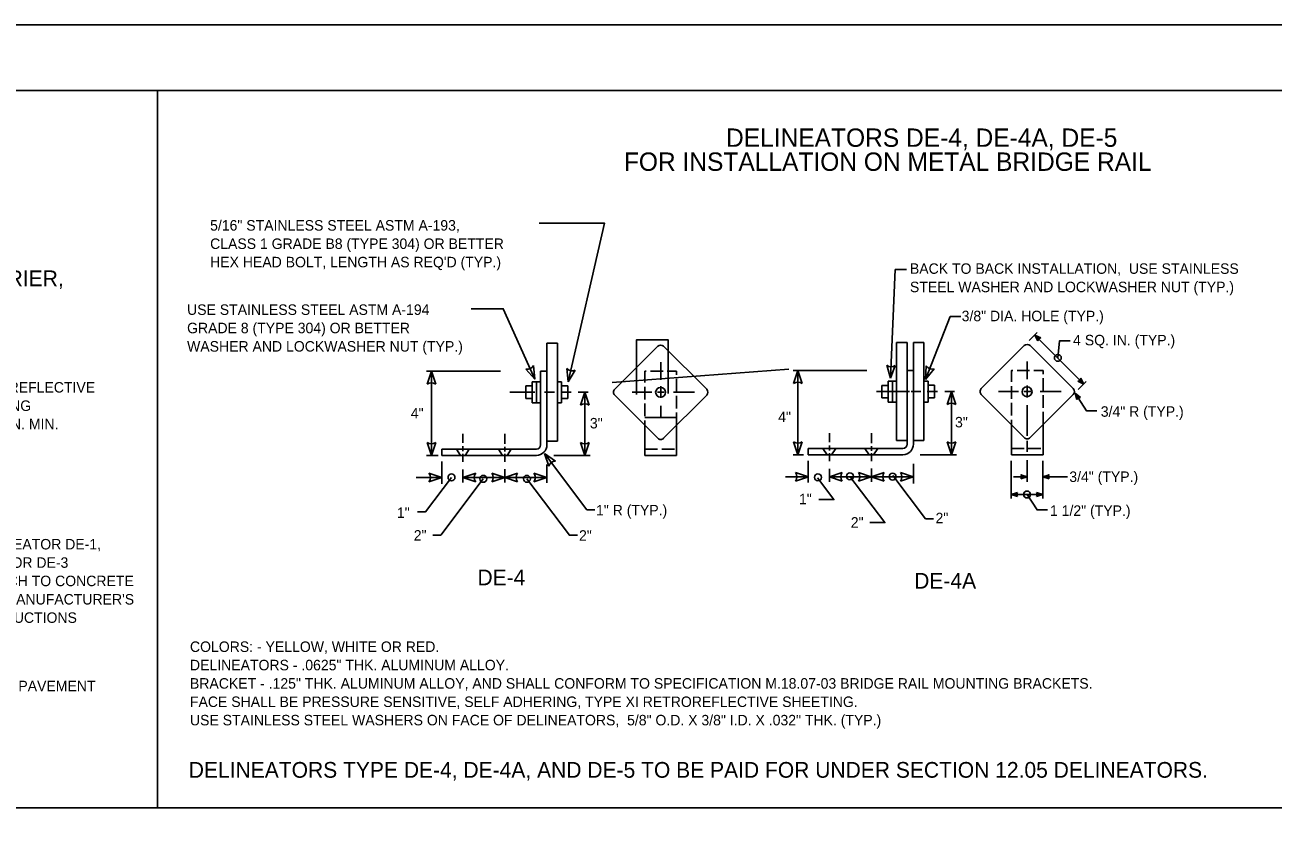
# Model space of a CAD drawing. Extents: x -0.14 to 2.7, y -0.05 to 1.78.
# Drawn here: x 1.18 to 2.172, y 1.149 to 1.781 of the extents above; entities that cross this region are included whole.
import ezdxf

# ---------------------------------------------------------------- set-up
doc = ezdxf.new("R2010")
doc.units = 0
for name, color, linetype in [('BDR_Outer_Perimeter', 7, 'Continuous'), ('BDR_Perimeter', 7, 'Continuous'), ('CT_CSHT_GeneralLabel', 7, 'Continuous')]:
    doc.layers.add(name, color=color, linetype=linetype)

msp = doc.modelspace()

# ---------------------------------------------------------------- linework, layer by layer
at = {"layer": 'BDR_Outer_Perimeter'}
msp.add_lwpolyline([(-0.13539, -0.05208), (2.69793, -0.05208), (2.69793, 1.78125), (-0.13539, 1.78125)], close=True, dxfattribs=at)
at = {"layer": 'BDR_Perimeter'}
msp.add_line((2.64583, 1.72917), (0, 1.72917), dxfattribs=at)
at = {"layer": 'CT_CSHT_GeneralLabel'}
for p, q in [((1.28552, 1.72917), (1.28552, 1.15912)), ((1.59489, 1.5283), (1.60324, 1.5283)), ((1.59489, 1.5283), (1.59489, 1.50606)), ((1.60324, 1.48935), (1.60324, 1.5283)), ((1.88117, 1.52882), (1.87281, 1.52882)), ((1.87281, 1.48987), (1.87281, 1.52882)), ((1.88117, 1.52882), (1.88117, 1.50658)), ((1.88618, 1.52882), (1.89454, 1.52882)), ((1.88618, 1.52882), (1.88618, 1.50658)), ((1.89454, 1.48987), (1.89454, 1.52882)), ((1.97819, 1.5304), (1.98462, 1.53684)), ((1.98266, 1.53488), (2.02161, 1.49592)), ((1.98502, 1.53015), (1.98266, 1.53488)), ((1.98266, 1.53488), (1.98739, 1.53252)), ((1.98266, 1.53488), (1.98579, 1.53171)), ((1.98266, 1.53488), (1.98535, 1.53117)), ((1.98266, 1.53488), (1.98651, 1.53223)), ((1.98266, 1.53488), (1.98517, 1.53079)), ((1.98266, 1.53488), (1.98558, 1.53148)), ((1.98266, 1.53488), (1.9861, 1.532)), ((1.98266, 1.53488), (1.98688, 1.5324)), ((1.68294, 1.52594), (1.64876, 1.49175)), ((1.72185, 1.49175), (1.68767, 1.52594)), ((1.97424, 1.52646), (1.94006, 1.49228)), ((2.01315, 1.49228), (1.97897, 1.52646)), ((1.57803, 1.50781), (1.58537, 1.49987)), ((1.57803, 1.50781), (1.57803, 1.50781)), ((1.58537, 1.49987), (1.58426, 1.51062)), ((1.61075, 1.50837), (1.61178, 1.49761)), ((1.61075, 1.50837), (1.61075, 1.50837)), ((1.7871, 1.50774), (1.64662, 1.49706)), ((1.6853, 1.49924), (1.6853, 1.51338)), ((1.86494, 1.51089), (1.8679, 1.50049)), ((1.86494, 1.51089), (1.86494, 1.51089)), ((1.8679, 1.50049), (1.87177, 1.51059)), ((1.89633, 1.51041), (1.89574, 1.49962)), ((1.89574, 1.49962), (1.90268, 1.5079)), ((1.89633, 1.51041), (1.89633, 1.51041)), ((1.9766, 1.49976), (1.9766, 1.51391)), ((1.55789, 1.50606), (1.49924, 1.50606)), ((1.5031, 1.50606), (1.49968, 1.49581)), ((1.5031, 1.43922), (1.5031, 1.50606)), ((1.50652, 1.49581), (1.5031, 1.50606)), ((1.58987, 1.50606), (1.58987, 1.44758)), ((1.58987, 1.50606), (1.59489, 1.50606)), ((1.59489, 1.44758), (1.59489, 1.50606)), ((1.61178, 1.49761), (1.61741, 1.50683)), ((1.84919, 1.50658), (1.79054, 1.50658)), ((1.7944, 1.50658), (1.79098, 1.49633)), ((1.7944, 1.43974), (1.7944, 1.50658)), ((1.79782, 1.49633), (1.7944, 1.50658)), ((1.86613, 1.49823), (1.86613, 1.48152)), ((1.86614, 1.49823), (1.86614, 1.48152)), ((1.86948, 1.49823), (1.86614, 1.49823)), ((1.87281, 1.49823), (1.86947, 1.49823)), ((1.87282, 1.49823), (1.86948, 1.49823)), ((1.86948, 1.49823), (1.86948, 1.48152)), ((1.88117, 1.50658), (1.88117, 1.4481)), ((1.88117, 1.50658), (1.88618, 1.50658)), ((1.88618, 1.4481), (1.88618, 1.50658)), ((1.89453, 1.49823), (1.89788, 1.49823)), ((1.89788, 1.49823), (1.89788, 1.48152)), ((2.02161, 1.49592), (2.01689, 1.49829)), ((2.0171, 1.4915), (2.02352, 1.49793)), ((2.02161, 1.49592), (2.0174, 1.4984)), ((2.02161, 1.49592), (2.01777, 1.49857)), ((2.02161, 1.49592), (2.01818, 1.49881)), ((2.02161, 1.49592), (2.01849, 1.49909)), ((2.02161, 1.49592), (2.0187, 1.49932)), ((2.02161, 1.49592), (2.01892, 1.49964)), ((2.02161, 1.49592), (2.0191, 1.50002)), ((2.01925, 1.50065), (2.02161, 1.49592)), ((1.50652, 1.49581), (1.50652, 1.49581)), ((1.56554, 1.48935), (1.58525, 1.48935)), ((1.57818, 1.49436), (1.58319, 1.49436)), ((1.57818, 1.49436), (1.57818, 1.48434)), ((1.58319, 1.4977), (1.58319, 1.48099)), ((1.58653, 1.4977), (1.58319, 1.4977)), ((1.58653, 1.4977), (1.58653, 1.48099)), ((1.58987, 1.4977), (1.58653, 1.4977)), ((1.60083, 1.48935), (1.59304, 1.48935)), ((1.60324, 1.4977), (1.60658, 1.4977)), ((1.60324, 1.45049), (1.60324, 1.48935)), ((1.60587, 1.48935), (1.61412, 1.48935)), ((1.60658, 1.4977), (1.60658, 1.48099)), ((1.61159, 1.49436), (1.60658, 1.49436)), ((1.61159, 1.49436), (1.61159, 1.48434)), ((1.61985, 1.48935), (1.62761, 1.48935)), ((1.62504, 1.48935), (1.62162, 1.4791)), ((1.62504, 1.43922), (1.62504, 1.48935)), ((1.62845, 1.4791), (1.62504, 1.48935)), ((1.66259, 1.48935), (1.67828, 1.48935)), ((1.68266, 1.48935), (1.68806, 1.48935)), ((1.6853, 1.49416), (1.6853, 1.48483)), ((1.71225, 1.48935), (1.69552, 1.48935)), ((1.79782, 1.49633), (1.79782, 1.49633)), ((1.85694, 1.48987), (1.87655, 1.48987)), ((1.861, 1.49486), (1.86614, 1.49486)), ((1.861, 1.49486), (1.861, 1.48483)), ((1.87281, 1.45101), (1.87281, 1.48987)), ((1.87522, 1.48987), (1.88301, 1.48987)), ((1.89213, 1.48987), (1.88434, 1.48987)), ((1.89454, 1.45101), (1.89454, 1.48987)), ((1.89717, 1.48987), (1.90542, 1.48987)), ((1.90289, 1.49489), (1.89788, 1.49489)), ((1.90289, 1.49489), (1.90289, 1.48486)), ((1.91115, 1.48987), (1.91891, 1.48987)), ((1.91634, 1.48987), (1.91292, 1.47962)), ((1.91634, 1.43974), (1.91634, 1.48987)), ((1.91975, 1.47962), (1.91634, 1.48987)), ((1.95388, 1.48987), (1.96958, 1.48987)), ((1.97396, 1.48987), (1.97936, 1.48987)), ((1.9766, 1.49469), (1.9766, 1.48535)), ((2.00354, 1.48987), (1.98682, 1.48987)), ((2.01605, 1.48353), (2.01477, 1.48866)), ((2.01477, 1.48866), (2.01887, 1.48533)), ((2.01477, 1.48866), (2.01714, 1.48489)), ((2.01477, 1.48866), (2.01659, 1.48445)), ((2.01477, 1.48866), (2.01796, 1.48524)), ((2.01477, 1.48866), (2.01634, 1.48412)), ((2.01477, 1.48866), (2.01688, 1.48471)), ((2.01477, 1.48866), (2.0175, 1.4851)), ((2.01477, 1.48866), (2.01835, 1.48532)), ((1.57818, 1.48434), (1.58319, 1.48434)), ((1.58319, 1.48099), (1.58653, 1.48099)), ((1.58653, 1.48099), (1.58987, 1.48099)), ((1.60658, 1.48099), (1.60324, 1.48099)), ((1.61159, 1.48434), (1.60658, 1.48434)), ((1.62845, 1.4791), (1.62845, 1.4791)), ((1.64876, 1.48703), (1.68294, 1.45285)), ((1.6853, 1.46881), (1.6853, 1.47868)), ((1.68767, 1.45285), (1.72185, 1.48703)), ((1.861, 1.48483), (1.86614, 1.48483)), ((1.86948, 1.48152), (1.86614, 1.48152)), ((1.86947, 1.48152), (1.87281, 1.48152)), ((1.86948, 1.48152), (1.87282, 1.48152)), ((1.89788, 1.48152), (1.89453, 1.48152)), ((1.90289, 1.48486), (1.89788, 1.48486)), ((1.91975, 1.47962), (1.91975, 1.47962)), ((1.94006, 1.48755), (1.97424, 1.45338)), ((1.9766, 1.45474), (1.9766, 1.47921)), ((1.97897, 1.45338), (2.01315, 1.48755)), ((1.69784, 1.4693), (1.67277, 1.4693)), ((1.67277, 1.43922), (1.67277, 1.46267)), ((1.69784, 1.43922), (1.69784, 1.46294)), ((1.96407, 1.43974), (1.96407, 1.4632)), ((1.98914, 1.43974), (1.98914, 1.46346)), ((1.49969, 1.44947), (1.5031, 1.43922)), ((1.49969, 1.44947), (1.49969, 1.44947)), ((1.5031, 1.43922), (1.50652, 1.44947)), ((1.52805, 1.45627), (1.52805, 1.44917)), ((1.56147, 1.45627), (1.56147, 1.44848)), ((1.59489, 1.45049), (1.60324, 1.45049)), ((1.62162, 1.44947), (1.62504, 1.43922)), ((1.62162, 1.44947), (1.62162, 1.44947)), ((1.62504, 1.43922), (1.62845, 1.44947)), ((1.79098, 1.45), (1.7944, 1.43974)), ((1.79098, 1.45), (1.79098, 1.45)), ((1.7944, 1.43974), (1.79782, 1.45)), ((1.81935, 1.4568), (1.81935, 1.44969)), ((1.85276, 1.4568), (1.85276, 1.449)), ((1.88117, 1.45101), (1.87281, 1.45101)), ((1.88618, 1.45101), (1.89454, 1.45101)), ((1.91292, 1.45), (1.91634, 1.43974)), ((1.91292, 1.45), (1.91292, 1.45)), ((1.91634, 1.43974), (1.91975, 1.45)), ((1.9766, 1.4421), (1.9766, 1.45074)), ((1.50851, 1.43922), (1.49924, 1.43922)), ((1.51134, 1.44423), (1.51134, 1.43922)), ((1.51134, 1.44423), (1.58653, 1.44423)), ((1.51134, 1.43922), (1.58653, 1.43922)), ((1.52626, 1.4392), (1.52295, 1.44412)), ((1.52805, 1.44252), (1.52805, 1.44664)), ((1.52805, 1.43404), (1.52805, 1.44057)), ((1.52983, 1.4392), (1.53314, 1.44412)), ((1.55968, 1.4392), (1.55637, 1.44412)), ((1.56147, 1.44229), (1.56147, 1.44607)), ((1.56147, 1.43404), (1.56147, 1.44046)), ((1.56324, 1.4392), (1.56656, 1.44412)), ((1.60178, 1.43466), (1.59288, 1.44078)), ((1.59288, 1.44078), (1.59633, 1.43054)), ((1.60034, 1.43922), (1.62915, 1.43922)), ((1.67277, 1.43922), (1.69784, 1.43922)), ((1.79891, 1.43974), (1.79054, 1.43974)), ((1.80264, 1.44476), (1.80264, 1.43974)), ((1.80264, 1.44476), (1.87783, 1.44476)), ((1.80264, 1.43974), (1.87783, 1.43974)), ((1.81757, 1.43972), (1.81425, 1.44465)), ((1.81935, 1.44304), (1.81935, 1.44717)), ((1.81935, 1.43457), (1.81935, 1.4411)), ((1.82113, 1.43972), (1.82444, 1.44465)), ((1.85098, 1.43972), (1.84767, 1.44465)), ((1.85276, 1.44282), (1.85276, 1.4466)), ((1.85276, 1.43457), (1.85276, 1.44098)), ((1.85455, 1.43972), (1.85786, 1.44465)), ((1.89164, 1.43974), (1.92045, 1.43974)), ((1.96407, 1.43974), (1.98914, 1.43974)), ((1.51134, 1.43446), (1.51134, 1.41656)), ((1.59489, 1.43198), (1.59489, 1.41747)), ((1.60178, 1.43466), (1.60178, 1.43466)), ((1.80264, 1.43498), (1.80264, 1.41761)), ((1.81935, 1.41813), (1.81935, 1.42849)), ((1.85276, 1.41813), (1.85276, 1.42872)), ((1.88618, 1.4325), (1.88618, 1.417)), ((1.96378, 1.43485), (1.96378, 1.40489)), ((1.9766, 1.41813), (1.9766, 1.43554)), ((1.98897, 1.40489), (1.98897, 1.43485)), ((1.51138, 1.4217), (1.49105, 1.4217)), ((1.51138, 1.4217), (1.50113, 1.42512)), ((1.50113, 1.41829), (1.51138, 1.4217)), ((1.52805, 1.41761), (1.52805, 1.42797)), ((1.53834, 1.42512), (1.52809, 1.4217)), ((1.52809, 1.4217), (1.56136, 1.4217)), ((1.52809, 1.4217), (1.53834, 1.41829)), ((1.53834, 1.42512), (1.53834, 1.42512)), ((1.56136, 1.4217), (1.55111, 1.42512)), ((1.55111, 1.41829), (1.56136, 1.4217)), ((1.57161, 1.42512), (1.56136, 1.4217)), ((1.56136, 1.4217), (1.59478, 1.4217)), ((1.56136, 1.4217), (1.57161, 1.41829)), ((1.56147, 1.41761), (1.56147, 1.42819)), ((1.57161, 1.42512), (1.57161, 1.42512)), ((1.59478, 1.4217), (1.58453, 1.42512)), ((1.58453, 1.41829), (1.59478, 1.4217)), ((1.80268, 1.42223), (1.78457, 1.42223)), ((1.80268, 1.42223), (1.79243, 1.42565)), ((1.79243, 1.41881), (1.80268, 1.42223)), ((1.79243, 1.41881), (1.79243, 1.41881)), ((1.82964, 1.42565), (1.81939, 1.42223)), ((1.81939, 1.42223), (1.85266, 1.42223)), ((1.81939, 1.42223), (1.82964, 1.41881)), ((1.82964, 1.42565), (1.82964, 1.42565)), ((1.85266, 1.42223), (1.84241, 1.42565)), ((1.84241, 1.41881), (1.85266, 1.42223)), ((1.84241, 1.41881), (1.84241, 1.41881)), ((1.86291, 1.42565), (1.85266, 1.42223)), ((1.85266, 1.42223), (1.88608, 1.42223)), ((1.85266, 1.42223), (1.86291, 1.41881)), ((1.86291, 1.42565), (1.86291, 1.42565)), ((1.88608, 1.42223), (1.87583, 1.42565)), ((1.87583, 1.41881), (1.88608, 1.42223)), ((1.87583, 1.41881), (1.87583, 1.41881)), ((1.96574, 1.42223), (1.9766, 1.42223)), ((1.97159, 1.4239), (1.9766, 1.42223)), ((1.9766, 1.42223), (1.97159, 1.42056)), ((1.9766, 1.42223), (1.97187, 1.421)), ((1.9766, 1.42223), (1.97193, 1.42335)), ((1.9766, 1.42223), (1.97201, 1.42138)), ((1.9766, 1.42223), (1.97208, 1.42295)), ((1.9766, 1.42223), (1.97214, 1.42257)), ((1.9766, 1.42223), (1.97214, 1.42184)), ((1.9766, 1.42223), (1.97215, 1.42225)), ((1.98897, 1.42223), (1.99399, 1.4239)), ((1.98897, 1.42223), (1.99371, 1.42346)), ((1.98897, 1.42223), (1.99356, 1.42308)), ((1.98897, 1.42223), (1.99344, 1.42262)), ((1.99399, 1.42056), (1.98897, 1.42223)), ((1.98897, 1.42223), (1.99342, 1.42221)), ((1.98897, 1.42223), (1.99351, 1.42151)), ((1.98897, 1.42223), (1.99364, 1.42111)), ((1.98897, 1.42223), (1.99344, 1.42189)), ((1.98897, 1.42223), (2.00859, 1.42223)), ((1.50113, 1.41829), (1.50113, 1.41829)), ((1.55111, 1.41829), (1.55111, 1.41829)), ((1.58453, 1.41829), (1.58453, 1.41829)), ((1.96378, 1.40817), (1.96879, 1.40984)), ((1.96378, 1.40817), (1.96852, 1.4094)), ((1.96378, 1.40817), (1.96837, 1.40902)), ((1.96378, 1.40817), (1.96825, 1.40856)), ((1.98396, 1.40984), (1.98897, 1.40817)), ((1.98897, 1.40817), (1.9843, 1.40929)), ((1.98897, 1.40817), (1.98444, 1.40889)), ((1.98897, 1.40817), (1.98451, 1.40851)), ((1.96378, 1.40817), (1.98897, 1.40817)), ((1.96879, 1.4065), (1.96378, 1.40817)), ((1.96378, 1.40817), (1.96823, 1.40815)), ((1.96378, 1.40817), (1.96831, 1.40745)), ((1.96378, 1.40817), (1.96845, 1.40705)), ((1.96378, 1.40817), (1.96825, 1.40783)), ((1.98897, 1.40817), (1.98396, 1.4065)), ((1.98897, 1.40817), (1.98424, 1.40694)), ((1.98897, 1.40817), (1.98438, 1.40732)), ((1.98897, 1.40817), (1.98451, 1.40778)), ((1.98897, 1.40817), (1.98452, 1.40819)), ((2.64583, 1.15912), (0, 1.15912))]:
    msp.add_line(p, q, dxfattribs=at)
for points in [[(1.61178, 1.49761), (1.64078, 1.62374), (1.58885, 1.62374)], [(1.8679, 1.50049), (1.87171, 1.58682), (1.88056, 1.58682)], [(1.53476, 1.55569), (1.56017, 1.55569), (1.58537, 1.49987)], [(1.89574, 1.49962), (1.91544, 1.54947), (1.92379, 1.54947)], [(1.66609, 1.48773), (1.66609, 1.53112), (1.69115, 1.53112), (1.69115, 1.48827)], [(2.01064, 1.53025), (2.00228, 1.53025), (2.00093, 1.51672)], [(1.67386, 1.50606), (1.67277, 1.50606), (1.67277, 1.49712)], [(1.68722, 1.50606), (1.6772, 1.50606)], [(1.69784, 1.50331), (1.69784, 1.50606), (1.69056, 1.50606)], [(1.69784, 1.48994), (1.69784, 1.49996)], [(1.96515, 1.50658), (1.96407, 1.50658), (1.96407, 1.49764)], [(1.97852, 1.50658), (1.9685, 1.50658)], [(1.98914, 1.50383), (1.98914, 1.50658), (1.98186, 1.50658)], [(1.98914, 1.49046), (1.98914, 1.50049)], [(1.67277, 1.49378), (1.67277, 1.48375)], [(1.96407, 1.4943), (1.96407, 1.48427)], [(2.01477, 1.48866), (2.02368, 1.47464), (2.03204, 1.47464)], [(1.67277, 1.48041), (1.67277, 1.47038)], [(1.69784, 1.47657), (1.69784, 1.4866)], [(1.96407, 1.48093), (1.96407, 1.47091)], [(1.98914, 1.4771), (1.98914, 1.48712)], [(1.69784, 1.4632), (1.69784, 1.47323)], [(1.98914, 1.46373), (1.98914, 1.47376)], [(1.67277, 1.46704), (1.67277, 1.46267)], [(1.96407, 1.46756), (1.96407, 1.4632)], [(1.63302, 1.39595), (1.62671, 1.39595), (1.59288, 1.44078)], [(1.67277, 1.44423), (1.6828, 1.44423)], [(1.68614, 1.44423), (1.69617, 1.44423)], [(1.96407, 1.44476), (1.9741, 1.44476)], [(1.97744, 1.44476), (1.98747, 1.44476)], [(1.4921, 1.39437), (1.49842, 1.39437), (1.51906, 1.42173)], [(1.50417, 1.37574), (1.51049, 1.37574), (1.54432, 1.42058)], [(1.61911, 1.37574), (1.6128, 1.37574), (1.57897, 1.42058)], [(1.81106, 1.40409), (1.82302, 1.40409), (1.8099, 1.42148)], [(1.85149, 1.38583), (1.86346, 1.38583), (1.83574, 1.42257)], [(1.90212, 1.38884), (1.8958, 1.38884), (1.86992, 1.42315)], [(1.97647, 1.40813), (1.98446, 1.39588), (1.99282, 1.39588)]]:
    msp.add_lwpolyline(points, dxfattribs=at)
for centre, radius in [((2.00093, 1.51672), 0.00275), ((1.68521, 1.48933), 0.00392), ((1.97648, 1.48979), 0.00392), ((1.51906, 1.42173), 0.00275), ((1.54432, 1.42058), 0.00275), ((1.57897, 1.42058), 0.00275), ((1.81029, 1.42178), 0.00275), ((1.83574, 1.42257), 0.00275), ((1.8696, 1.4223), 0.00275), ((1.97647, 1.40813), 0.00275)]:
    msp.add_circle(centre, radius, dxfattribs=at)
for centre, radius, start, end in [((1.98774, 1.5298), 0.00274, 97.39918, 172.60081), ((1.68531, 1.52357), 0.00334, 45.0072, 135), ((1.9766, 1.5241), 0.00334, 45.0072, 135), ((1.57932, 1.51326), 0.0056, 256.69293, 331.89456), ((1.61508, 1.51192), 0.0056, 219.45094, 294.65257), ((1.86855, 1.51517), 0.0056, 229.8764, 305.07803), ((1.90114, 1.51328), 0.0056, 210.83412, 286.03575), ((2.01654, 1.501), 0.00274, 277.39918, 352.60081), ((1.5031, 1.49137), 0.0056, 52.40233, 127.60396), ((1.65113, 1.48939), 0.00334, 135, 225.00529), ((1.71949, 1.48939), 0.00334, 315, 44.98661), ((1.7944, 1.49189), 0.0056, 52.40233, 127.60396), ((1.94242, 1.48992), 0.00334, 135, 225.00529), ((2.01078, 1.48992), 0.00334, 315, 44.98661), ((1.62504, 1.47466), 0.0056, 52.40128, 127.60291), ((1.91634, 1.47518), 0.0056, 52.39918, 127.60081), ((2.01863, 1.4826), 0.00274, 84.82044, 160.02208), ((1.5031, 1.45391), 0.0056, 232.40233, 307.60396), ((1.62504, 1.45391), 0.0056, 232.40128, 307.60291), ((1.68531, 1.45521), 0.00334, 224.98983, 314.99317), ((1.7944, 1.45444), 0.0056, 232.40233, 307.60396), ((1.91634, 1.45444), 0.0056, 232.39918, 307.60081), ((1.97661, 1.45574), 0.00334, 224.98983, 314.99317), ((1.58653, 1.44758), 0.00835, 270, 359.99999), ((1.58653, 1.44758), 0.00334, 270, 359.99999), ((1.87783, 1.4481), 0.00835, 270, 359.99999), ((1.87783, 1.4481), 0.00334, 270, 359.99999), ((1.60173, 1.42906), 0.0056, 89.43028, 164.63191), ((1.49669, 1.4217), 0.0056, 322.39918, 37.60081), ((1.54278, 1.4217), 0.0056, 142.39918, 217.60081), ((1.54667, 1.4217), 0.0056, 322.39918, 37.60081), ((1.57605, 1.4217), 0.0056, 142.39918, 217.60081), ((1.58009, 1.4217), 0.0056, 322.39918, 37.60081), ((1.78799, 1.42223), 0.0056, 322.39918, 37.60081), ((1.83408, 1.42223), 0.0056, 142.39918, 217.60081), ((1.83797, 1.42223), 0.0056, 322.39918, 37.60081), ((1.86735, 1.42223), 0.0056, 142.39918, 217.60081), ((1.87139, 1.42223), 0.0056, 322.39918, 37.60081), ((1.96942, 1.42223), 0.00274, 322.39918, 37.60081), ((1.99616, 1.42223), 0.00274, 142.39918, 217.60081), ((1.97096, 1.40817), 0.00274, 142.39918, 217.60081), ((1.98179, 1.40817), 0.00274, 322.39918, 37.60081)]:
    msp.add_arc(centre, radius, start, end, dxfattribs=at)

# ---------------------------------------------------------------- texts
for s, height, p in [('DELINEATORS DE-4, DE-4A, DE-5', 0.0145833, (1.73722, 1.68441)), ('FOR INSTALLATION ON METAL BRIDGE RAIL', 0.0145833, (1.65605, 1.66533)), ('5/16" STAINLESS STEEL ASTM A-193,', 0.0083333, (1.32723, 1.61784)), ('CLASS 1 GRADE B8 (TYPE 304) OR BETTER', 0.0083333, (1.32723, 1.60326)), ("HEX HEAD BOLT, LENGTH AS REQ'D (TYP.)", 0.0083333, (1.32723, 1.58867)), ('BACK TO BACK INSTALLATION,  USE STAINLESS', 0.0083333, (1.88338, 1.58349)), ('PERMANENT CONCRETE BARRIER,', 0.0125, (0.92392, 1.57368)), ('STEEL WASHER AND LOCKWASHER NUT (TYP.)', 0.0083333, (1.88338, 1.56891)), ('USE STAINLESS STEEL ASTM A-194', 0.0083333, (1.30893, 1.55086)), ('3/8" DIA. HOLE (TYP.)', 0.0083333, (1.9245, 1.54583)), ('GRADE 8 (TYPE 304) OR BETTER', 0.0083333, (1.30893, 1.53628)), ('WASHER AND LOCKWASHER NUT (TYP.)', 0.0083333, (1.30893, 1.52169)), ('4 SQ. IN. (TYP.)', 0.0083333, (2.01306, 1.52666)), ('RETROREFLECTIVE', 0.0083333, (1.12808, 1.48914)), ('SHEETING', 0.008333, (1.12808, 1.47455)), ('3/4" R (TYP.)', 0.0083333, (2.03505, 1.46991)), ('16 SQ. IN. MIN.', 0.0083333, (1.12808, 1.45997)), ('4"', 0.008333, (1.48671, 1.46855)), ('3"', 0.008333, (1.62906, 1.46064)), ('4"', 0.008333, (1.77867, 1.46564)), ('3"', 0.008333, (1.91924, 1.46145)), ('3/4" (TYP.)', 0.0083333, (2.01004, 1.41812)), ('1"', 0.008333, (1.79522, 1.4004)), ('1" R (TYP.)', 0.0083333, (1.63393, 1.39149)), ('1 1/2" (TYP.)', 0.0083333, (1.99469, 1.39117)), ('1" ', 0.008333, (1.47571, 1.38949)), ('2"', 0.008333, (1.83638, 1.3818)), ('2"', 0.008333, (1.90374, 1.38529)), ('2"', 0.008333, (1.48905, 1.37148)), ('2" ', 0.008333, (1.62041, 1.37142)), ('DELINEATOR DE-1, ', 0.0083333, (1.13779, 1.36447)), ('DE-2, OR DE-3', 0.0083333, (1.13779, 1.34988)), ('ATTACH TO CONCRETE', 0.0083333, (1.13779, 1.3353)), ('DE-4', 0.0125, (1.53969, 1.336)), ('DE-4A', 0.0125, (1.88676, 1.33334)), ("PER MANUFACTURER'S", 0.0083333, (1.13779, 1.32072)), ('INSTRUCTIONS', 0.0083333, (1.13779, 1.30613)), ('COLORS: - YELLOW, WHITE OR RED.', 0.0083333, (1.31122, 1.28303)), ('DELINEATORS - .0625" THK. ALUMINUM ALLOY.', 0.0083333, (1.31122, 1.26844)), ('PAVEMENT', 0.008333, (1.17484, 1.25183)), ('BRACKET - .125" THK. ALUMINUM ALLOY, AND SHALL CONFORM TO SPECIFICATION M.18.07-03 BRIDGE RAIL MOUNTING BRACKETS.', 0.00833333, (1.31122, 1.25386)), ('FACE SHALL BE PRESSURE SENSITIVE, SELF ADHERING, TYPE XI RETROREFLECTIVE SHEETING.', 0.0083333, (1.31122, 1.23928)), ('USE STAINLESS STEEL WASHERS ON FACE OF DELINEATORS,  5/8" O.D. X 3/8" I.D. X .032" THK. (TYP.)', 0.0083333, (1.31122, 1.22469)), ('DELINEATORS TYPE DE-4, DE-4A, AND DE-5 TO BE PAID FOR UNDER SECTION 12.05 DELINEATORS.', 0.0125, (1.31027, 1.18307))]:
    msp.add_text(s, height=height, dxfattribs=at).set_placement(p)

doc.saveas('drawing.dxf')
